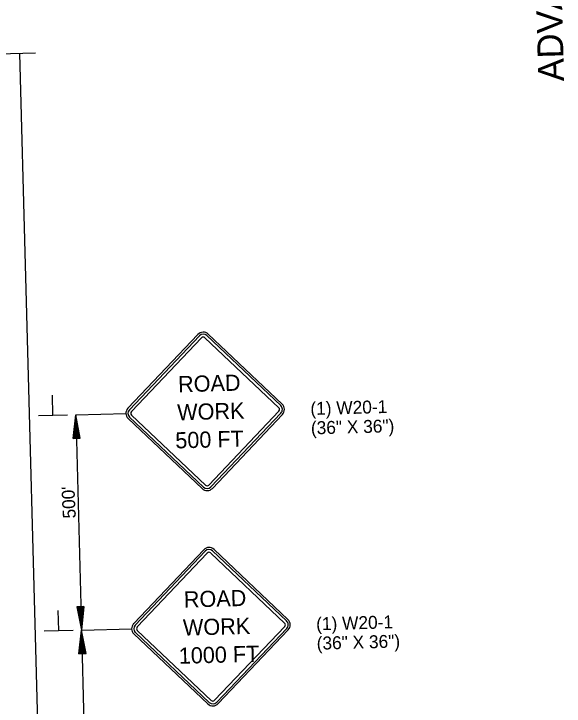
# Model space of a CAD drawing. Extents: x 1929653 to 1931621, y 596452 to 600944.
# Drawn here: x 1930892.7 to 1931148, y 599903.1 to 600224.5 of the extents above; entities that cross this region are included whole.
import ezdxf

# ---------------------------------------------------------------- set-up
doc = ezdxf.new("R2010")
doc.units = 0
for name, color, linetype in [('P_TC_Signs_Temporary', 7, 'Continuous'), ('R_Border', 7, 'Continuous'), ('R_Draft', 7, 'Continuous')]:
    doc.layers.add(name, color=color, linetype=linetype)

msp = doc.modelspace()

# ---------------------------------------------------------------- linework, layer by layer
at = {"layer": 'P_TC_Signs_Temporary'}
for p, q in [((1930982.9, 600075.77), (1931017.2, 600043.27)), ((1930945.63, 600041.35), (1930978.13, 600075.64)), ((1930946.31, 600040.7), (1930978.81, 600075)), ((1930947.26, 600039.8), (1930979.77, 600074.09)), ((1930981.36, 600074.14), (1931015.65, 600041.63)), ((1930982.26, 600075.09), (1931016.55, 600042.59)), ((1930980.7, 600004.75), (1930946.4, 600037.26)), ((1930981.6, 600005.71), (1930947.31, 600038.21)), ((1931015.69, 600040.04), (1930983.19, 600005.75)), ((1931016.65, 600039.14), (1930984.14, 600004.85)), ((1931017.33, 600038.5), (1930984.82, 600004.2)), ((1930980.05, 600004.07), (1930945.76, 600036.58)), ((1930948.31, 599941.38), (1930980.82, 599975.68)), ((1930948.99, 599940.74), (1930981.5, 599975.03)), ((1930949.95, 599939.84), (1930982.45, 599974.13)), ((1930984.04, 599974.17), (1931018.33, 599941.67)), ((1930984.94, 599975.13), (1931019.24, 599942.62)), ((1930985.59, 599975.81), (1931019.88, 599943.3)), ((1930984.28, 599905.74), (1930949.99, 599938.24)), ((1931018.38, 599940.08), (1930985.88, 599905.79)), ((1931019.33, 599939.18), (1930986.83, 599904.88)), ((1931020.01, 599938.53), (1930987.51, 599904.24)), ((1930982.74, 599904.11), (1930948.44, 599936.61)), ((1930983.38, 599904.79), (1930949.09, 599937.29))]:
    msp.add_line(p, q, dxfattribs=at)
for centre, radius, start, end in [((1930980.58, 600073.32), 3.38, 46.5377, 136.5377), ((1930980.58, 600073.32), 2.44, 46.5377, 136.5377), ((1930980.58, 600073.32), 1.13, 46.5377, 136.5377), ((1930948.08, 600039.03), 3.38, 136.5377, 226.5377), ((1930948.08, 600039.03), 2.44, 136.5377, 226.5377), ((1931014.88, 600040.82), 1.12, 316.5377, 46.5377), ((1931014.88, 600040.82), 2.44, 316.5377, 46.5377), ((1931014.88, 600040.82), 3.38, 316.5377, 46.5377), ((1930948.08, 600039.03), 1.12, 136.5377, 226.5377), ((1930982.38, 600006.52), 1.13, 226.5377, 316.5377), ((1930982.38, 600006.52), 3.38, 226.5377, 316.5377), ((1930982.38, 600006.52), 2.44, 226.5377, 316.5377), ((1930983.27, 599973.36), 3.38, 46.5377, 136.5377), ((1930983.27, 599973.36), 2.44, 46.5377, 136.5377), ((1930983.27, 599973.36), 1.13, 46.5377, 136.5377), ((1930950.76, 599939.06), 3.38, 136.5377, 226.5377), ((1931017.56, 599940.85), 1.12, 316.5377, 46.5377), ((1931017.56, 599940.85), 2.44, 316.5377, 46.5377), ((1931017.56, 599940.85), 3.38, 316.5377, 46.5377), ((1930950.76, 599939.06), 2.44, 136.5377, 226.5377), ((1930950.76, 599939.06), 1.12, 136.5377, 226.5377), ((1930985.06, 599906.56), 1.13, 226.5377, 316.5377), ((1930985.06, 599906.56), 3.38, 226.5377, 316.5377), ((1930985.06, 599906.56), 2.44, 226.5377, 316.5377)]:
    msp.add_arc(centre, radius, start, end, dxfattribs=at)
at = {"layer": 'R_Draft'}
for p, q in [((1930902.74, 600206.32), (1930868.3, 600205.4)), ((1930898.19, 600107.92), (1930895.55, 600206.13)), ((1930909.83, 599674.07), (1930898.19, 600107.92)), ((1930910.86, 600038.22), (1930910.62, 600047.41)), ((1930917.57, 600038.21), (1930904.11, 600037.84)), ((1930920.26, 600027.37), (1930921.42, 600038.31)), ((1930921.42, 600038.31), (1930944.71, 600038.93)), ((1930921.42, 600038.31), (1930924.1, 599938.35)), ((1930923.52, 600027.51), (1930921.42, 600038.31)), ((1930920.53, 600027.38), (1930921.5, 600036.49)), ((1930920.8, 600027.39), (1930921.58, 600034.63)), ((1930923.25, 600027.5), (1930921.5, 600036.49)), ((1930922.97, 600027.48), (1930921.58, 600034.63)), ((1930921.08, 600027.41), (1930921.66, 600032.81)), ((1930921.36, 600027.42), (1930921.73, 600030.97)), ((1930922.7, 600027.47), (1930921.66, 600032.81)), ((1930922.42, 600027.46), (1930921.73, 600030.97)), ((1930921.63, 600027.43), (1930921.81, 600029.16)), ((1930922.14, 600027.45), (1930921.81, 600029.16)), ((1930920.26, 600027.37), (1930923.52, 600027.51)), ((1930913.55, 599938.26), (1930913.3, 599947.44)), ((1930925.26, 599949.28), (1930922, 599949.15)), ((1930922, 599949.15), (1930924.1, 599938.35)), ((1930922.28, 599949.16), (1930924.02, 599940.16)), ((1930922.56, 599949.17), (1930923.94, 599942.03)), ((1930922.83, 599949.18), (1930923.86, 599943.84)), ((1930923.1, 599949.19), (1930923.79, 599945.68)), ((1930923.38, 599949.21), (1930923.71, 599947.5)), ((1930923.89, 599949.23), (1930923.71, 599947.5)), ((1930924.16, 599949.24), (1930923.79, 599945.68)), ((1930924.44, 599949.25), (1930923.86, 599943.84)), ((1930924.72, 599949.26), (1930923.94, 599942.03)), ((1930925, 599949.27), (1930924.02, 599940.16)), ((1930925.26, 599949.28), (1930924.1, 599938.35)), ((1930920.25, 599938.24), (1930906.79, 599937.88)), ((1930922.94, 599927.41), (1930924.1, 599938.35)), ((1930924.1, 599938.35), (1930947.39, 599938.97)), ((1930924.1, 599938.35), (1930926.81, 599838.5)), ((1930926.2, 599927.54), (1930924.1, 599938.35)), ((1930923.21, 599927.42), (1930924.18, 599936.53)), ((1930923.49, 599927.43), (1930924.26, 599934.66)), ((1930925.93, 599927.53), (1930924.18, 599936.53)), ((1930925.65, 599927.52), (1930924.26, 599934.66)), ((1930923.76, 599927.44), (1930924.34, 599932.85)), ((1930925.38, 599927.51), (1930924.34, 599932.85)), ((1930924.04, 599927.45), (1930924.42, 599931.01)), ((1930924.31, 599927.47), (1930924.5, 599929.19)), ((1930925.1, 599927.5), (1930924.42, 599931.01)), ((1930924.82, 599927.48), (1930924.5, 599929.19)), ((1930922.94, 599927.41), (1930926.2, 599927.54))]:
    msp.add_line(p, q, dxfattribs=at)

# ---------------------------------------------------------------- texts
at = {"layer": 'P_TC_Signs_Temporary'}
for s, p in [(' ROAD ', (1930966.22, 600048.73)), ('WORK', (1930968.6, 600035.76)), ('500 FT ', (1930967.73, 600022.71)), (' ROAD ', (1930968.9, 599948.76)), ('WORK', (1930971.28, 599935.8)), ('1000 FT', (1930969.33, 599922.72))]:
    msp.add_text(s, height=7.5, rotation=1.5377, dxfattribs=at).set_placement(p)
at = {"layer": 'R_Border'}
for s, height, rotation, p in [('ADVANCE WARNING DETAILS', 12, 91.5377, (1931148.03, 600193.26)), ('(1) W20-1', 6, 1.5377, (1931030.38, 600038.23)), ('(36" X 36")', 6, 1.5377, (1931030.62, 600029.24)), ('(1) W20-1', 6, 1.5377, (1931033.06, 599938.27)), ('(36" X 36")', 6, 1.5377, (1931033.3, 599929.27))]:
    msp.add_text(s, height=height, rotation=rotation, dxfattribs=at).set_placement(p)
at = {"layer": 'R_Draft'}
msp.add_text("500'", height=6, rotation=92.7681, dxfattribs=at).set_placement((1930921.51, 599990.33))

doc.saveas('drawing.dxf')
